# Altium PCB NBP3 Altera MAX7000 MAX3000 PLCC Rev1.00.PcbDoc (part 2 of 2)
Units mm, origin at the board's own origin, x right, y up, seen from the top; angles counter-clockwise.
Board outline 69 x 80.99 mm, 2 copper layers (Top Layer, Bottom Layer); 33 components, 75 nets, 412 pads, 171 vias.
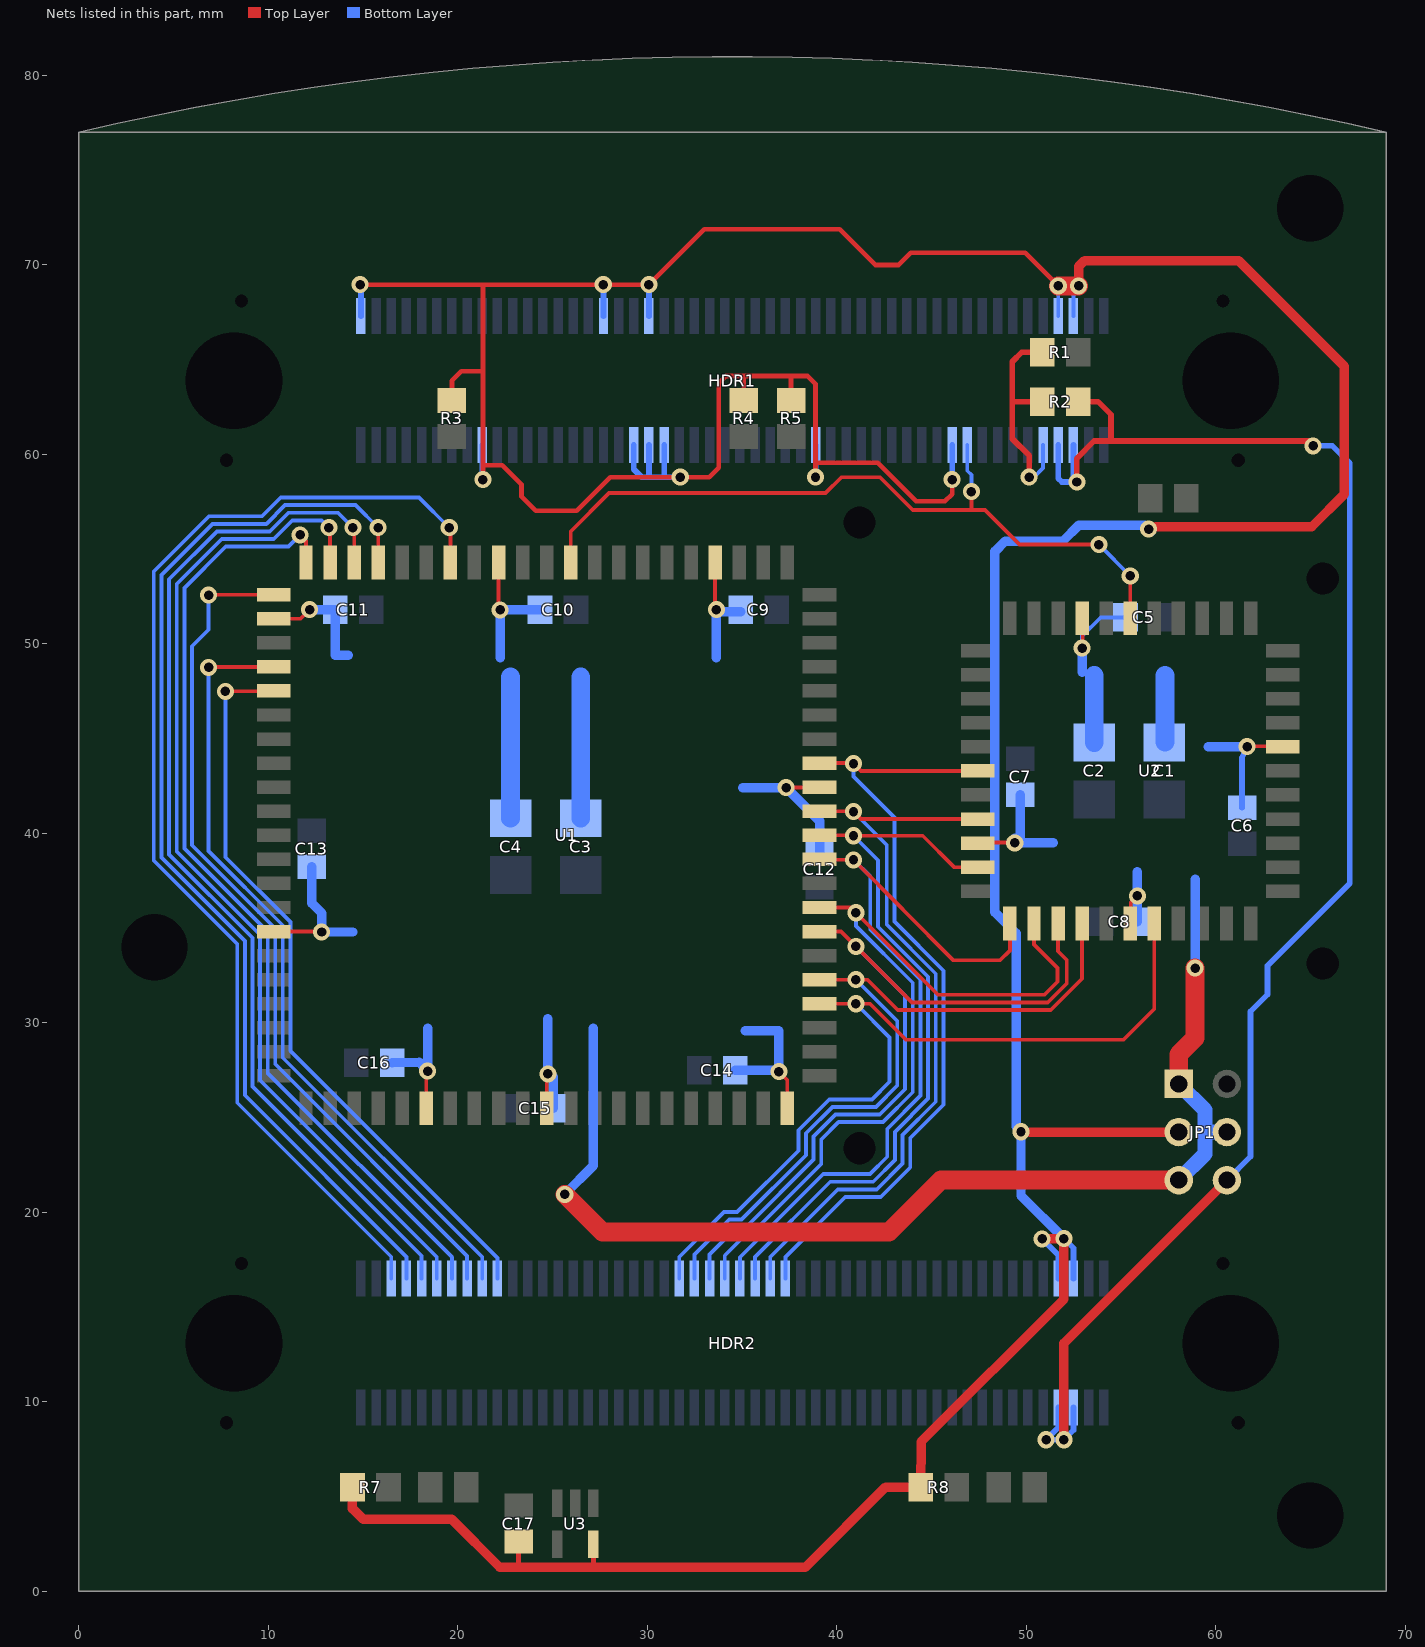
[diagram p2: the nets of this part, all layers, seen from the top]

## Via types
v1: diameter 0.9, hole 0.5, Top Layer to Bottom Layer, 165 vias
v2: diameter 1.27, hole 0.7, Top Layer to Bottom Layer, 6 vias

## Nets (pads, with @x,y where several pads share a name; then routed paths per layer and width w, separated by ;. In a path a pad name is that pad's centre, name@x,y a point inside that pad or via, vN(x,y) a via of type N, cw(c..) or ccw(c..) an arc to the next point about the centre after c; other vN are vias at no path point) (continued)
SW0: HDR2.44 U1.57 U2.24 | length 45.2
  Top Layer w0.2: U1.57@39.1,31.01 41.761,31.01 43.656,29.115 55.15,29.115 56.77,30.735 U2.24@56.77,35.25
  Bottom Layer w0.2: HDR2.44@31.7,16.5 31.7,17.653 34.064,20.017 34.749,20.017 37.986,23.254 37.986,24.338 39.613,25.965 41.865,25.965 42.799,26.899 42.799,29.232 v1(41.021,31.01)
SW1: HDR2.46 U1.58 U2.21 | length 41
  Top Layer w0.2: U1.58@39.1,32.28 41.634,32.28 43.231,30.683 51.308,30.683 52.96,32.335 U2.21@52.96,35.25
  Bottom Layer w0.2: HDR2.46@32.5,16.5 32.5,17.78 34.337,19.617 34.984,19.617 38.386,23.019 38.386,24.172 39.779,25.565 42.075,25.565 43.205,26.695 43.205,30.096 v1(41.021,32.28)
SW2: HDR2.48 U1.60 U2.20 | length 42.9
  Top Layer w0.2: U1.60@39.1,34.82 40.237,34.82 43.974,31.083 51.142,31.083 52.146,32.087 52.146,33.326 51.69,33.782 U2.20@51.69,35.25
  Bottom Layer w0.2: HDR2.48@33.3,16.5 33.3,17.78 34.737,19.217 35.219,19.217 38.786,22.784 38.786,24.007 39.944,25.165 42.278,25.165 43.612,26.499 43.612,31.445 v1(41.021,34.036)
SW3: HDR2.50 U1.61 U2.19 | length 44.5
  Top Layer w0.2: U1.61@39.1,36.09 40.745,36.09 45.352,31.483 50.977,31.483 51.664,32.17 51.664,32.893 50.42,34.137 U2.19@50.42,35.25
  Bottom Layer w0.2: HDR2.50@34.1,16.5 34.1,17.717 35.2,18.817 35.454,18.817 39.192,22.555 39.192,23.847 40.11,24.765 42.443,24.765 44.018,26.34 44.018,32.119 41.021,35.117 v1(41.021,35.814)
SW4: HDR2.52 U1.63 U2.18 | length 42.9
  Top Layer w0.2: U1.63@39.1,38.63 v1(40.894,38.608) 46.139,33.312 48.641,33.312 49.15,33.821 U2.18@49.15,35.25
  Bottom Layer w0.2: HDR2.52@34.9,16.5 34.9,17.628 39.294,22.022 41.758,22.022 42.672,22.936 42.672,24.409 44.425,26.162 44.425,32.279 41.783,34.92 41.783,37.719 v1(40.894,38.608)
SW5: HDR2.54 U1.64 U2.16 | length 39.2
  Top Layer w0.2: U1.64@39.1,39.9 40.872,39.9 v1(40.894,39.878) 44.545,39.878 46.203,38.22 U2.16@47.45,38.22
  Bottom Layer w0.2: HDR2.54@35.7,16.5 35.7,17.653 39.662,21.615 41.935,21.615 43.078,22.758 43.078,24.25 44.831,26.003 44.831,32.438 42.189,35.08 42.189,38.583 v1(40.894,39.878)
SW6: HDR2.56 U1.65 U2.14 | length 39.8
  Top Layer w0.2: U1.65@39.1,41.17 40.872,41.17 41.282,40.76 U2.14@47.45,40.76
  Bottom Layer w0.2: HDR2.56@36.5,16.5 36.5,17.653 40.062,21.215 42.12,21.215 43.485,22.581 43.485,24.091 45.237,25.843 45.237,32.597 42.647,35.188 42.647,39.395 v1(40.894,41.148)
SW7: HDR2.58 U1.67 U2.12 | length 42.2
  Top Layer w0.2: U1.67@39.1,43.71 40.872,43.71 41.282,43.3 U2.12@47.45,43.3
  Bottom Layer w0.2: HDR2.58@37.3,16.5 37.3,17.653 40.462,20.815 42.329,20.815 43.891,22.377 43.891,23.932 45.644,25.684 45.644,32.757 43.053,35.347 43.053,40.841 40.894,43 v1(40.894,43.688)
SWC0: HDR2.18 U1.15 | length 41.7
  Top Layer w0.2: v1(6.858,48.768) 6.88,48.79 U1.15@10.3,48.79
  Bottom Layer w0.2: v1(6.858,48.768) 6.858,39.069 10.775,35.153 10.775,28.163 21.3,17.638 HDR2.18@21.3,16.5
SWC1: HDR2.16 U1.12 | length 45.9
  Top Layer w0.2: v1(6.858,52.578) v1@6.88,52.578 ; v1@6.88,52.6 U1.12@10.3,52.6
  Bottom Layer w0.2: v1(6.858,52.578) 6.858,50.749 5.988,49.879 5.988,39.374 10.375,34.987 10.375,27.827 20.5,17.702 HDR2.16@20.5,16.5
SWC2: HDR2.14 U1.11 | length 51.3
  Top Layer w0.2: v1(11.684,55.753) 12,55.437 U1.11@12,54.3 ; U1.11@12.065,54.102 U1.11@12.065,54.3
  Bottom Layer w0.2: v1(11.684,55.753) 11.068,55.137 7.766,55.137 5.588,52.959 5.588,39.208 9.975,34.821 9.975,27.363 19.7,17.638 HDR2.14@19.7,16.5
SWC3: HDR2.6 U1.5 | length 62.3
  Top Layer w0.2: v1(19.558,56.134) 19.62,56.072 U1.5@19.62,54.3
  Bottom Layer w0.2: HDR2.6@16.5,16.5 16.5,17.663 8.375,25.788 8.375,34.159 3.962,38.571 3.962,53.823 6.877,56.737 9.671,56.737 10.668,57.734 17.958,57.734 v1(19.558,56.134)
SWR0: HDR2.20 U1.16 | length 39.5
  Top Layer w0.2: v1@7.769,47.52 v1(7.747,47.498) U1.16@10.3,47.52
  Bottom Layer w0.2: v1(7.747,47.498) 7.747,38.746 11.175,35.318 11.175,28.525 22.1,17.6 HDR2.20@22.1,16.5
SWR1: HDR2.12 U1.10 | length 53.8
  Top Layer w0.2: v1(13.208,56.134) 13.27,56.072 U1.10@13.27,54.3
  Bottom Layer w0.2: v1(13.208,56.134) 12.827,56.515 11.278,56.515 10.3,55.537 7.556,55.537 5.182,53.162 5.182,39.049 9.575,34.656 9.575,26.978 18.9,17.653 HDR2.12@18.9,16.5
SWR2: HDR2.10 U1.9 | length 55.8
  Top Layer w0.2: U1.9@14.54,54.3 14.54,56.072 v1(14.478,56.134) v1@14.54,56.174
  Bottom Layer w0.2: v1(14.478,56.134) 13.691,56.921 11.074,56.921 10.09,55.937 7.296,55.937 4.775,53.416 4.775,38.89 9.175,34.49 9.175,26.639 18.1,17.714 HDR2.10@18.1,16.5
SWR3: HDR2.8 U1.8 | length 57.8
  Top Layer w0.2: U1.8@15.81,54.3 v1(15.81,56.134)
  Bottom Layer w0.2: v1(15.81,56.134) 14.616,57.328 10.897,57.328 9.906,56.337 7.061,56.337 4.369,53.645 4.369,38.73 8.775,34.324 8.775,26.178 17.3,17.653 HDR2.8@17.3,16.5
TEST: HDR1.81 U1.84 U2.1 | length 40.3
  Top Layer w0.2: U1.84@25.97,54.3 25.97,55.942 27.991,57.963 39.421,57.963 40.259,58.801 42.291,58.801 44.018,57.074 47.828,57.074 49.657,55.245 v1(53.848,55.245) ; 47.117,57.074 v1(47.117,58.039) ; v1(55.499,53.594) v1(55.499,53.594) U2.1@55.5,51.35
  Bottom Layer w0.2: HDR1.81@46.9,60.5 46.9,59.145 47.117,58.928 v1(47.117,58.039) ; v1(53.848,55.245) v1(55.499,53.594)
VCC: C17.1 HDR1.2 HDR1.17 HDR1.34 HDR1.37 HDR1.39 HDR1.40 HDR1.41 HDR1.61 HDR1.79 HDR1.94 HDR1.96 HDR2.94 HDR2.96 JP1.3 R3.1 R4.1 R5.1 R7.1 R8.1 U3.5 | length 264.8
  Top Layer w0.25: v1(14.859,68.961) v1(30.099,68.961) 33.02,71.882 40.157,71.882 42.037,70.002 43.272,70.002 43.919,70.65 49.95,70.65 v1(51.7,68.9) ; R3.1@19.7,62.85 19.7,63.896 20.193,64.389 21.336,64.389 ; v1(21.336,58.674) 21.336,68.961 ; 21.336,59.436 22.352,59.436 23.368,58.42 23.368,57.785 24.13,57.023 26.289,57.023 28.067,58.801 33.274,58.801 33.782,59.309 33.782,63.754 34.163,64.135 38.481,64.135 38.887,63.729 v1(38.887,58.801) ; 23.217,1.27 C17.1@23.217,2.621 ; 27.167,1.27 U3.5@27.167,2.496 ; R4.1@35.1,62.85 35.1,64.135 ; R5.1@37.6,62.85 37.6,64.135 ; 38.887,59.563 42.164,59.563 44.196,57.531 45.72,57.531 46.101,57.912 v1(46.101,58.674)
  Top Layer w0.5: R7.1@14.45,5.5 14.45,4.369 15.009,3.81 19.685,3.81 22.225,1.27 38.354,1.27 42.584,5.5 R8.1@44.45,5.5 44.463,7.892 51.994,15.418 v1(51.994,18.618) ; 50.207,24.24 JP1.3@58.06,24.24 ; v1(50.851,18.6) v1@51.975,18.6 ; v1(52.775,68.9) 52.775,69.92 53.086,70.231 61.214,70.231 66.802,64.643 66.802,57.912 65.075,56.185 56.871,56.185 v1(56.464,56.058)
  Top Layer w1: v1(51.7,68.9) v1(52.775,68.9)
  Bottom Layer w0.2: HDR1.94@51.7,67.3 v1(51.7,68.9) ; HDR1.96@52.5,67.3 52.5,68.625 v1(52.775,68.9)
  Bottom Layer w0.3: HDR1.2@14.9,67.3 v1@14.9,68.92 ; v1@21.3,58.71 HDR1.17@21.3,60.5 ; HDR1.34@27.7,67.3 v1@27.7,68.947 ; HDR1.37@29.3,60.5 29.3,59.219 29.718,58.801 v1(31.75,58.801) ; 30.1,58.801 HDR1.39@30.1,60.5 ; HDR1.40@30.1,67.3 v1(30.099,68.961) ; 30.9,58.801 HDR1.41@30.9,60.5 ; v1@38.9,58.814 HDR1.61@38.9,60.5 ; v1(46.101,58.674) HDR1.79@46.1,60.5 ; v1(50.851,18.6) 51.7,17.751 HDR2.94@51.7,16.5 ; v1(51.994,18.618) 52.5,18.112 HDR2.96@52.5,16.5
  Bottom Layer w0.5: v1(51.994,18.618) 49.733,20.879 v1(49.733,24.257) 49.479,24.511 49.479,34.722 48.359,35.842 48.359,54.887 48.891,55.419 51.939,55.419 52.79,56.27 56.252,56.27 v1@56.591,55.931
  other v1: 27.686,68.961
VCC_FPGA: C1.1 C2.1 C3.1 C4.1 C5.1 C6.1 C7.1 C8.1 C9.2 C10.2 C11.2 C12.1 C13.2 C14.1 C15.1 C16.1 JP1.1 JP1.4 JP1.5 U1.3 U1.13 U1.26 U1.38 U1.43 U1.53 U1.66 U1.78 U2.3 U2.15 U2.23 U2.35 | length 166.8
  Top Layer w0.2: U1.26@10.3,34.82 v1@12.805,34.82 ; U1.13@10.3,51.33 11.706,51.33 v1(12.192,51.816) ; U1.38@18.35,25.5 18.35,27.113 v1(18.415,27.457) ; U1.3@22.16,54.3 22.16,51.881 v1(22.241,51.8) ; 24.7,26.732 U1.43@24.7,25.5 24.7,27.24 v1(24.765,27.305) ; U1.78@33.59,54.3 33.59,51.881 v1(33.655,51.816) ; v1(36.957,27.432) 37.4,26.989 U1.53@37.4,25.5 ; v1(37.338,42.418) 39.078,42.418 U1.66@39.1,42.44 ; U2.15@47.478,39.524 v1@49.122,39.524 ; v1@52.988,49.813 U2.3@52.988,51.384 ; U2.23@55.528,35.284 55.528,36.351 v1(55.88,36.703) ; v1(61.671,44.577) 62.003,44.604 U2.35@63.578,44.604
  Top Layer w1: v1(25.654,20.955) 27.635,18.974 42.774,18.974 45.5,21.7 JP1.5@58.06,21.7 ; JP1.1@58.06,26.78 58.06,28.342 58.928,29.21 v1(58.928,32.893)
  Bottom Layer w0.2: v1(52.959,49.784) 52.959,50.419 53.94,51.4 C5.1@55.25,51.4
  Bottom Layer w0.3: C6.1@61.4,41.35 61.4,44.001 v1(61.671,44.577)
  Bottom Layer w0.5: v1@12.208,51.8 C11.2@13.55,51.8 13.55,49.403 14.224,49.403 ; C13.2@12.3,38.25 12.3,36.322 12.827,35.795 v1(12.827,34.798) 14.478,34.798 ; C16.1@16.55,27.9 17.983,27.915 v1@18.372,27.5 ; v1(18.415,27.457) 18.415,29.718 ; 22.241,49.276 v1(22.241,51.8) C10.2@24.35,51.8 ; v1(24.765,27.305) 24.765,30.226 ; C15.1@25.05,25.5 v1@25.05,27.15 ; v1(25.654,20.955) 27.153,22.454 27.153,29.718 ; 33.655,49.276 v1(33.655,51.816) 33.771,51.7 C9.2@34.95,51.7 ; C14.1@34.65,27.5 36.889,27.5 v1(36.957,27.432) 36.957,29.591 35.179,29.591 ; 35.052,42.418 v1(37.338,42.418) 39.1,40.656 C12.1@39.1,39.05 ; v1@49.4,39.748 v1(49.403,39.497) ; C7.1@49.7,42.05 49.7,39.794 v1(49.403,39.497) ; 51.435,39.497 v1(49.403,39.497) ; 52.959,48.514 v1(52.959,49.784) ; C8.1@55.878,35.334 v1@55.878,36.701 ; v1(55.88,36.703) 55.88,37.973 ; v1(58.928,32.893) 58.928,37.592 ; 59.614,44.577 v1(61.671,44.577)
  Bottom Layer w0.8: JP1.5@58.06,21.7 59.436,23.076 59.436,25.404 JP1.1@58.06,26.78 ; 59.453,24.24 JP1.4@60.6,24.24
  Bottom Layer w1: C4.1@22.8,40.8 22.8,48.26 ; C3.1@26.5,40.8 26.5,48.26 ; C2.1@53.6,44.8 53.6,48.325 ; C1.1@57.328,44.834 57.328,48.336
VCCINT: HDR1.93 HDR1.95 HDR2.93 HDR2.95 JP1.6 R2.1 | length 90.3
  Top Layer w0.3: v1(52.68,58.547) 52.68,59.792 53.594,60.706 64.897,60.706 v1(65.151,60.452) ; R2.1@52.75,62.787 53.799,62.787 54.483,62.103 54.483,60.706
  Top Layer w0.5: v1(51.994,8.001) 51.994,13.094 JP1.6@60.6,21.7
  Bottom Layer w0.3: HDR1.93@51.7,60.5 51.7,58.739 51.892,58.547 v1(52.68,58.547) 52.5,58.727 HDR1.95@52.5,60.5 ; HDR2.95@52.5,9.7 52.5,8.507 v1(51.994,8.001) ; JP1.6@60.6,21.7 61.849,22.949 61.849,30.607 62.738,31.496 62.738,33.02 67.081,37.363 67.081,59.538 66.167,60.452 v1(65.151,60.452) ; v1(51.054,8.001) 51.7,8.647 ; v1(51.054,8.001) v1(51.994,8.001) ; v1(51.054,8.001) 51.7,8.647 ; v1(51.054,8.001) v1(51.994,8.001) ; 51.7,8.647 HDR2.93@51.7,9.7 51.7,8.647
VREF: HDR1.91 R1.1 R2.2 | length 12
  Top Layer w0.3: 49.276,62.787 R2.2@50.85,62.787 ; v1(50.165,58.801) 50.165,59.944 49.276,60.833 49.276,64.897 49.779,65.4 R1.1@50.85,65.4
  Bottom Layer w0.2: v1(50.165,58.801) 50.419,58.801 50.9,59.282 HDR1.91@50.9,60.5
pads on no net: HDR1.3 HDR1.4 HDR1.5 HDR1.6 HDR1.8 HDR1.9 HDR1.10 HDR1.11 HDR1.12 HDR1.13 HDR1.14 HDR1.16 HDR1.18 HDR1.20 HDR1.22 HDR1.24 HDR1.26 HDR1.28 HDR1.30 HDR1.32 HDR1.43 HDR1.44 HDR1.45 HDR1.46 HDR1.47 HDR1.48 HDR1.49 HDR1.50 HDR1.51 HDR1.52 HDR1.53 HDR1.55 HDR1.56 HDR1.57 HDR1.58 HDR1.60 HDR1.62 HDR1.64 HDR1.66 HDR1.68 HDR1.76 HDR1.80 HDR1.82 HDR1.83 HDR1.84 HDR1.85 HDR1.86 HDR1.87 HDR1.88 HDR1.89 HDR1.90 HDR1.92 HDR1.MH1 HDR1.MH2 HDR1.MH3 HDR1.MH4 HDR1.MH5 HDR1.MH6 HDR2.3 HDR2.5 HDR2.43 HDR2.45 HDR2.47 HDR2.49 HDR2.51 HDR2.53 HDR2.55 HDR2.57 HDR2.59 HDR2.61 HDR2.63 HDR2.65 HDR2.67 HDR2.69 HDR2.71 HDR2.73 HDR2.75 HDR2.76 HDR2.77 HDR2.78 HDR2.79 HDR2.80 HDR2.81 HDR2.82 HDR2.83 HDR2.84 HDR2.85 HDR2.86 HDR2.87 HDR2.88 HDR2.89 HDR2.90 HDR2.91 HDR2.92 HDR2.MH1 HDR2.MH2 HDR2.MH3 HDR2.MH4 HDR2.MH5 HDR2.MH6 U1.6 U1.39 U1.46 U1.79 U1.M1 U1.M2 U2.M1 U2.M2 U3.1

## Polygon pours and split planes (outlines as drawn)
GND on Top Layer "Top Layer-GND" (solid, remove dead copper, pour order 1000): 0.127,80.518 68.834,80.645 68.834,0.127 0.127,0.127
GND on Bottom Layer "Bottom Layer-GND" (solid, remove dead copper, pour order 1001): 0.127,80.518 68.834,80.645 68.834,0.127 0.127,0.127

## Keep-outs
Keep-Out Layer:
  the board outline again, w0.8

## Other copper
Bottom Layer:
  rectangle net VCC_FPGA: 33.655,29.21 35.56,48.133
  rectangle net VCC_FPGA: 13.97,29.21 15.875,48.133
  rectangle net VCC_FPGA: 13.97,47.752 35.56,49.657
  rectangle net VCC_FPGA: 15.494,29.21 34.036,31.115
  region net VCC_FPGA: 51.816,48.133 50.673,48.133 50.673,38.608 51.816,38.608
  rectangle net VCC_FPGA: 59.182,38.608 60.325,48.133
  rectangle net VCC_FPGA: 50.673,37.465 60.325,38.735
  rectangle net VCC_FPGA: 50.673,47.752 60.325,49.022

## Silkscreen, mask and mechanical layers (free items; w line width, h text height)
Top Overlay:
  circle w0.127: c4,34 r2.5
  circle w0.127: c65,4 r2.5
  circle w0.127: c65,73 r2.5
  lines w0.127: 0,1.5 1.5,1.5 1.5,0 ; 0,22.3 1.5,22.3 1.5,23.4 0,23.4 ; 0.001,53.6 1.501,53.6 1.501,54.7 0.001,54.7 ; 0,75.5 1.5,75.5 1.5,77.3 ; 15.7,79.8 15.7,78.1 17,78.1 17,79.9 ; 49.7,80.2 49.7,78.7 51,78.7 51,80.1 ; 67.5,0 67.5,1.5 69,1.5 ; 67.5,77.3 67.5,75.5 69,75.5 ; 68.999,22.3 67.5,22.3 67.5,23.4 69,23.4 ; 69,53.6 67.501,53.6 67.501,54.7 69.001,54.7
  lines w0.2: 43.963,21.7 54.885,21.7 56.155,22.97 56.409,22.97 ; 43.963,26.78 54.885,26.78 56.155,25.51 56.409,25.51 ; 56.409,20.43 56.155,20.43 54.885,19.16 43.963,19.16 43.963,29.32 54.885,29.32 56.155,28.05 56.409,28.05 ; 62.251,20.43 66.188,20.43 66.188,28.05 62.251,28.05 ; 62.251,22.97 66.188,22.97 ; 62.251,25.51 66.188,25.51
  text "MAX7000S" at 44.852,27.415 h1.2
  text "5V" at 63.14,26.145 h1.2
  text "MAX3000A" at 44.852,24.875 h1.2
  text "3V3" at 62.632,23.605 h1.2
  text "MAX7000AE" at 44.852,22.335 h1.2
  text "2V5" at 62.632,21.065 h1.2
  text "MAX7000B" at 44.852,19.795 h1.2
Bottom Overlay:
  drawing of 853 lines, arcs and shapes, not listed
  text "REV 1.00" at 47.6,76.5 h1.3
  text "NBP3" at 54.5,76.5 h1.3
  text "1" at 13.97,58.42 h1
  text "1" at 14.224,7.62 h1
PCB Boundary:
  the board outline again, w0.25
  text "PCB boundary coincides with centre-line of tracks and arc" at 0,-12 h0.75
Gerber ID:
  text ".Layer_Name" at 0,-6 h0.75
Printout ID:
  text ".Printout_Name" at 0,-10 h0.75
Design Information:
  drawing of 713 lines, arcs and shapes, not listed
  text "BOCD_1_00_Daughter_NBP3" at 317.627,202.041 h1.27
  text "DESIGN INFORMATION" at 261.62,201.914 h1.52
  text "BOARD NAME:" at 299.212,201.914 h1.52
  text "BOARD TECHNOLOGY" at 261.62,199.374 h1.52
  text "BOARD SIZE (REFER ALSO PROFILING INFORMATION)" at 309.88,199.374 h1.27
  text "69.00mm" at 312.6,197.1 h1.52
  text "19.685" at 277.419,197.012 h1.52
  text "81.00mm" at 335.6,197 h1.52
  text "7.874" at 291.389,196.885 h1.52
  text "7.874" at 264.446,196.834 h1.52
  text "X" at 328.549,196.326 h1.78
  text "(MIN. TRACK/   PADS  /   CLEARANCE     IN 0.001'')" at 260.096,194.294 h1.27
  text "MINIMUM ANNULAR RING 0.05MM (0.002'') EXTERNAL PER IPC-2221 CLASS 3 LEVEL C AND IS THE" at 261.62,191.754 h1.27
  text "MANUFACTURING REGISTRATION ALLOWANCE" at 261.62,189.468 h1.27
  text "LAND SIZE CALCULATION MINIMUM - NOMINAL HOLE SIZE + 0.508MM (0.020'')" at 261.62,186.674 h1.27
  text "AS INSTRUCTED" at 347.65,182.28 h1.52
  text "X" at 299.263,182.153 h1.52
  text "CIRCUIT TYPE:" at 261.62,182.102 h1.52
  text "SS" at 284.48,182.102 h1.27
  text "DS" at 302.26,182.102 h1.27
  text "X" at 316.865,182.102 h1.52
  text "PTH" at 320.04,182.102 h1.27
  text "ML" at 330.962,182.102 h1.27
  text "No. OFF" at 337.82,182.102 h1.27
  text "FINGER CONNECTOR DIM PER:" at 261.62,179.054 h1.52
  text "AS SHOWN" at 337.82,179.054 h1.27
  text "No. OFF TOTAL" at 278.384,176.26 h1.52
  text "ONE SIDE" at 320.04,176.26 h1.27
  text "BOTH SIDES" at 337.82,176.006 h1.27
  text "VIAS:" at 261.62,173.339 h1.52
  text "NONE" at 273.05,173.339 h1.14
  text "X" at 281.432,173.339 h1.52
  text "FEED THRU'" at 284.48,173.339 h1.14
  text "X" at 299.212,173.339 h1.52
  text "TENTED" at 302.26,173.339 h1.14
  text "UNIQUE DRILL" at 284.48,170.291 h1.14
  text "2 SIZE" at 302.26,170.291 h1.14
  text "BLIND LAYER SEQUENCE" at 320.04,170.291 h1.14
  text "Layer Stack Manager (Protel)" at 297.053,168.005 h1.27
  text "X" at 334.772,168.005 h1.52
  text "AS SHOWN" at 337.82,168.005 h1.27
  text "LAYER CONSTRUCTION PER:" at 261.62,167.878 h1.52
  text "Protel" at 342.646,165.338 h1.27
  text "(PFW)" at 352.933,165.211 h1.27
  text "ARTWORK:" at 261.62,165.084 h1.52
  text "MANUAL" at 284.48,165.084 h1.27
  text "DIGITISED" at 302.26,165.084 h1.27
  text "X" at 316.992,165.084 h1.52
  text "CAD" at 320.04,165.084 h1.27
  text "TYPE" at 330.962,165.084 h1.27
  text "ARTWORK/PATTERN MASTER LIST" at 261.62,160.385 h1.52
  text "DESCRIPTION" at 262.89,157.972 h1.27
  text "DRAWING No./CAD FILE REF." at 281.559,157.972 h1.27
  text "LAYER NAME" at 322.834,157.972 h1.27
  text "GERBER FILE REF" at 343.586,157.896 h1.27
  text "PCB FILE" at 261.366,155.432 h1.27
  text "BOCD_1_00_Daughter_NBP3" at 281.237,155.356 h1.27
  text "PcbDoc" at 312.979,155.356 h1.02
  text "Top Paste Mask" at 321.158,152.892 h1.02
  text "GTP" at 363.779,152.816 h1.27
  text "GERBER FILE" at 261.366,152.765 h1.27
  text "GTO" at 363.728,150.327 h1.27
  text "Top Overlay" at 321.158,150.301 h1.02
  text "GERBER FILE" at 261.366,150.225 h1.27
  text "Top Solder Mask" at 321.158,147.863 h1.02
  text "GTS" at 363.779,147.736 h1.27
  text "GERBER FILE" at 261.366,147.685 h1.27
  text "TOP LAYER" at 321.158,145.272 h1.02
  text "GTL" at 363.779,145.196 h1.27
  text "GERBER FILE" at 261.366,145.145 h1.27
  text "BOTTOMLAYER" at 321.158,142.732 h1.02
  text "GBL" at 363.779,142.656 h1.27
  text "GERBER FILE" at 261.366,142.605 h1.27
  text "Bottom Solder Mask" at 321.158,140.243 h1.02
  text "GBS" at 363.779,140.116 h1.27
  text "GERBER FILE" at 261.366,140.065 h1.27
  text "Bottom Overlay" at 321.158,137.652 h1.02
  text "GBO" at 363.779,137.576 h1.27
  text "GERBER FILE" at 261.366,137.525 h1.27
  text "Bottom Paste Mask" at 321.158,135.163 h1.02
  text "GBP" at 363.779,135.036 h1.27
  text "GERBER FILE" at 261.366,134.985 h1.27
  text "PCB Boundary" at 321.158,132.572 h1.02
  text "GM1" at 363.779,132.496 h1.27
  text "GERBER FILE" at 261.366,132.445 h1.27
  text "APERTURE LIST" at 261.366,130.032 h1.27
  text "APR" at 313.979,129.956 h1.27
  text "DRILL REPORT" at 261.366,127.492 h1.27
  text "DRR" at 313.979,127.416 h1.27
  text "EXCELLON DRILL" at 261.366,124.952 h1.27
  text "TXT" at 313.979,124.876 h1.27
  text "MATERIAL:" at 261.62,99.298 h1.52
  text "GLASS FIBRE EPOXY RESIN NEMA GRADE FR4 (MIL-S-13949H)" at 287.274,99.044 h1.27
  text "X" at 284.607,98.917 h1.52
  text "THICKNESS:" at 269.494,96.123 h1.27
  text "0.8mm" at 287.274,96.123 h1.27
  text "1.2mm" at 304.927,96.123 h1.27
  text "1.6mm" at 322.58,96.123 h1.27
  text "2.4mm" at 340.36,96.123 h1.27
  text "3.2mm" at 358.14,96.123 h1.27
  text "X" at 320.167,95.996 h1.52
  text "TOLERANCE:" at 269.367,93.075 h1.27
  text "IN A/W IPC-D-300G CLASS" at 287.02,93.075 h1.27
  text "3 LEVEL B" at 321.945,93.075 h1.27
  text "OTHER +/-" at 340.36,93.075 h1.27
  text "X" at 284.607,92.948 h1.52
  text "BOW & TWIST:" at 266.954,90.027 h1.27
  text "IN A/W IPC-D-300G CLASS" at 287.02,90.027 h1.27
  text "3 LEVEL B" at 321.945,90.027 h1.27
  text "AS SHOWN" at 340.487,89.9 h1.27
  text "X" at 284.607,89.773 h1.52
  text "COPPER THICKNESS (FINISHED)" at 269.367,86.725 h1.27
  text "OUTER:" at 274.193,84.439 h1.27
  text "18um" at 287.274,84.439 h1.27
  text "35um" at 314.325,84.439 h1.27
  text "70um" at 340.614,84.439 h1.27
  text "X" at 311.582,84.236 h1.52
  text "INNER SIGNAL:" at 265.811,81.391 h1.27
  text "18um" at 287.274,81.391 h1.27
  text "35um" at 314.325,81.391 h1.27
  text "70um" at 340.614,81.391 h1.27
  text "INNER PWR:" at 269.494,78.343 h1.27
  text "18um" at 287.274,78.343 h1.27
  text "35um" at 314.325,78.343 h1.27
  text "70um" at 340.614,78.343 h1.27
  text "STRUCTURE:" at 261.62,75.295 h1.52
  text "REFER" at 287.274,75.295 h1.27
  text "AS PER DRAWING No." at 287.147,72.12 h1.27
  text "AS SHOWN" at 340.487,72.12 h1.27
  text "X" at 337.947,71.993 h1.52
  text "DRILLING:" at 261.62,69.326 h1.52
  text "VIEWED FROM:" at 266.573,67.04 h1.27
  text "COMPONENT SIDE" at 287.274,67.04 h1.14
  text "SOLDER SIDE" at 314.071,67.04 h1.14
  text "X" at 284.607,66.786 h1.52
  text "REFERENCE:" at 268.859,63.992 h1.27
  text "AS SHOWN" at 287.147,63.865 h1.14
  text "PATTERN MASTER LIST" at 314.198,63.865 h1.14
  text "X" at 337.947,63.865 h1.52
  text "NC_DRILL FILES" at 340.487,63.865 h1.14
  text "X" at 284.607,63.738 h1.52
  text "PTH MINIMUM COPPER THICKNESS:" at 274.701,60.944 h1.27
  text "20um" at 314.325,60.944 h1.27
  text "X" at 311.658,60.817 h1.52
  text "OTHER" at 340.487,60.817 h1.27
  text "NPTH:" at 275.209,57.896 h1.27
  text "TENTED" at 287.147,57.769 h1.14
  text "X" at 311.658,57.769 h1.52
  text "PADS REMOVED" at 314.198,57.769 h1.14
  text "REMOVE PADS" at 340.487,57.769 h1.14
  text "X" at 284.607,57.642 h1.52
  text "2nd DRILL" at 287.147,54.721 h1.14
  text "BOTH" at 314.198,54.721 h1.14
  text "AS SHOWN" at 326.517,54.721 h1.14
  text "NONE" at 340.487,54.721 h1.14
  text "BOARD FINISH:" at 261.62,51.8 h1.52
  text "X" at 284.607,51.673 h1.52
  text "ETCHING" at 287.147,51.673 h1.14
  text "REFER PATTERN MASTER LIST" at 314.198,51.673 h1.14
  text "LEGEND / SCREEN PRINT:" at 281.94,48.752 h1.27
  text "NONE" at 314.198,48.625 h1.14
  text "COMPONENT" at 326.517,48.625 h1.14
  text "SOLDER" at 340.487,48.625 h1.14
  text "X" at 323.977,48.498 h1.52
  text "X" at 337.947,48.498 h1.52
  text "COLOUR:" at 272.161,45.704 h1.27
  text "WHITE" at 287.147,45.577 h1.14
  text "YELLOW" at 314.198,45.577 h1.14
  text "OTHER" at 340.487,45.577 h1.14
  text "X" at 284.607,45.45 h1.52
  text "X" at 284.607,42.529 h1.52
  text "LIQUID PHOTOIMAGEABLE" at 287.147,42.529 h1.14
  text "SCREEN PRINT" at 326.517,42.529 h1.14
  text "MATTE" at 287.147,39.481 h1.14
  text "GLOSS" at 299.847,39.481 h1.14
  text "GREEN" at 314.198,39.481 h1.14
  text "BLUE" at 326.517,39.481 h1.14
  text "G/Y" at 340.487,39.481 h1.14
  text "OTHER" at 351.917,39.481 h1.14
  text "X" at 297.18,39.354 h1.52
  text "SOLDER MASK COLOUR:" at 261.62,36.56 h1.14
  text "BLACK" at 287.147,36.433 h1.14
  text "GREEN" at 299.847,36.433 h1.14
  text "YELLOW" at 314.198,36.433 h1.14
  text "BLUE" at 326.517,36.433 h1.14
  text "OTHER" at 340.487,36.433 h1.14
  text "X" at 284.48,36.306 h1.52
  text "TRACK FINISH:" at 261.62,33.512 h1.52
  text "X" at 284.607,33.385 h1.52
  text "SELECTIVE SOLDER (HASL)" at 287.147,33.385 h1.14
  text "REFLOW SOLDER" at 326.517,33.385 h1.14
  text "SELECTIVE GOLD" at 287.147,30.337 h1.14
  text "um  (AREA" at 314.198,30.337 h1.14
  text "sq. mm)" at 342.011,30.337 h1.14
  text "REFER PATTERN MASTER LIST" at 287.147,27.289 h1.14
  text "OTHER" at 326.517,27.289 h1.14
  text "EDGE BOARD" at 261.62,24.368 h1.52
  text "1.3um HARD GOLD OVER 5um     NICKEL / TIN-NICKEL" at 287.147,24.241 h1.14
  text "CONTACTS:" at 261.62,22.209 h1.52
  text "HARD FINISH GOLDE PLATE" at 287.147,21.193 h1.14
  text "OTHER" at 326.517,21.193 h1.14
  text "AS SHOWN" at 287.147,18.145 h1.14
  text "REFER" at 326.517,18.145 h1.14
  text "PROFILING:" at 261.62,15.097 h1.52
  text "AS DIMENSIONED, MEASURED AND CUT FROM SPECIFIED DATUM." at 287.147,15.097 h1.14
  text "X" at 284.607,14.97 h1.52
  text "REFER PCB BLANK DWG No." at 287.274,12.176 h1.27
  text "USE PROFILE / ROUTE TAPE SUPPLIED (REFER PATTERN MASTER LIST)" at 287.274,9.128 h1.27
  text "SQUARE CUT" at 287.274,6.08 h1.27
  text "N.C. ROUTE" at 305.054,6.08 h1.27
  text "V. SCORE" at 322.834,6.08 h1.27
  text "BLANK" at 340.614,6.08 h1.27
  text "ACCEPTABILITY:" at 261.62,3.413 h1.52
  text "MATERIALS AND WORKMANSHIP FOR ALL PRINTED WIRING BOARDS TO MEET" at 283.845,3.286 h1.27
  text "OR EXCEED THE REQUIREMENTS OF:" at 283.845,0.492 h1.27
  text "IPC-6011/12 AND IPC-A-600E" at 287.401,-2.175 h1.27
  text "1" at 322.961,-2.175 h1.27
  text "2" at 331.851,-2.175 h1.27
  text "X" at 329.184,-2.302 h1.52
  text "X" at 284.734,-2.429 h1.52
  text "3" at 340.741,-4.334 h1.27
  text "UL CERTIFICATION" at 287.401,-5.223 h1.27
  text "AUSTEL" at 322.961,-5.223 h1.27
  text "X" at 284.734,-5.35 h1.52
  text "ML-P-55110F GRP" at 286.893,-8.271 h1.02
  text "A" at 305.181,-8.271 h1.27
  text "B" at 314.071,-8.271 h1.27
  text "AS2546" at 322.961,-8.271 h1.27
  text "OTHER" at 340.741,-8.271 h1.27
  text "ADDITIONAL" at 261.62,-11.192 h1.52
  text "NONE" at 287.401,-11.446 h1.27
  text "SAMPLE PLAN" at 305.181,-11.446 h1.27
  text "MIL-P-55110E SERIAL Nos. PER ORDER" at 322.961,-11.446 h1.27
  text "REQUIREMENTS:" at 261.62,-13.605 h1.52
  text "NONE" at 287.401,-14.494 h1.27
  text "ML-P-55110F GRP" at 304.673,-14.494 h1.02
  text "A" at 322.961,-14.494 h1.27
  text "B" at 331.851,-14.494 h1.27
  text "IPC CLASS:" at 337.82,-14.494 h1.27
  text "1" at 353.314,-14.494 h1.27
  text "2" at 359.664,-14.494 h1.27
  text "3" at 366.014,-14.494 h1.27
  text "QUALITY RELEASE REPORT" at 305.181,-17.542 h1.27
  text "OTHER" at 345.694,-17.542 h1.27
  text "PER ORDER" at 354.203,-17.669 h1.27
  text "X" at 343.027,-17.796 h1.52
  text "NONE" at 305.181,-20.59 h1.27
  text "REQUIRED" at 322.961,-20.59 h1.27
  text "PER ORDER" at 345.821,-20.59 h1.27
  text "ELECTRICAL TEST:" at 261.62,-20.717 h1.52
  text "X" at 320.294,-20.717 h1.52
  text "NONE" at 305.181,-23.638 h1.27
  text "1 SIDE" at 322.834,-23.638 h1.14
  text "2 SIDES" at 334.01,-23.638 h1.14
  text "MIN. PITCH" at 345.694,-23.638 h1.27
  text "0.80mm" at 359.283,-23.638 h1.27
  text "SURFACE MOUNT:" at 261.62,-23.765 h1.52
  text "X" at 331.775,-23.841 h1.52
  text "NONE" at 305.181,-26.686 h1.27
  text "FOIL" at 322.961,-26.686 h1.27
  text "LEGEND" at 334.391,-26.686 h1.27
  text "REFER" at 345.694,-26.686 h1.27
  text "MANUFACTURER'S ID/LOGO:" at 261.62,-26.813 h1.52
  text "ISO9001/AS3901" at 308.991,-29.734 h1.27
  text "NONE" at 345.694,-29.734 h1.27
  text "MANUFACTURER'S ACCREDITATION:" at 261.62,-29.861 h1.52
  text "X" at 306.324,-29.861 h1.52
  text "PER ORDER" at 305.181,-32.782 h1.27
  text "REFER" at 322.961,-32.782 h1.27
  text "PACKAGING AND HANDLING:" at 261.62,-32.909 h1.52
  text "X" at 302.514,-33.036 h1.52
Sheet:
  drawing of 1882 lines, arcs and shapes, not listed
  text "1" at 3.717,207.391 h1.78
  text "2" at 52.756,207.391 h1.78
  text "3" at 102.015,207.391 h1.78
  text "4" at 151.308,207.391 h1.78
  text "5" at 200.584,207.391 h1.78
  text "6" at 249.606,207.391 h1.78
  text "7" at 299.136,207.391 h1.78
  text "8" at 348.158,207.391 h1.78
  text "A" at -18.415,173.406 h1.78
  text "A" at 370.205,173.406 h1.78
  text "B" at -18.415,102.794 h1.78
  text "B" at 370.205,102.794 h1.78
  text "C" at -18.415,32.182 h1.78
  text "C" at 370.205,32.182 h1.78
  text "D" at -18.415,-37.922 h1.78
  text "D" at 370.205,-37.922 h1.78
  text "ENGINEER:" at 255.27,-38.1 h1.14
  text "TITLE:" at 293.37,-38.1 h1.14
  text "PCB DESIGNER:" at 255.27,-45.593 h1.14
  text "DATE:" at 255.27,-53.34 h1.14
  text "PART NO.:" at 293.37,-53.34 h1.14
  text "REV:" at 346.71,-53.34 h1.14
  text "Altium Limited" at 222.25,-55.88 h1.78
  text ".PRINT_DATE" at 256.54,-56.388 h1.78
  text "12a Rodborough Rd" at 222.25,-58.42 h1.78
  text "Frenchs Forest" at 222.25,-60.96 h1.78
  text "FILE NAME:" at 255.27,-60.96 h1.14
  text "DWG NO:" at 293.37,-60.96 h1.14
  text "SCALE:" at 346.71,-60.96 h1.14
  text "NSW 2086" at 222.25,-63.5 h1.78
  text ".PCB_FILE_NAME_NO_PATH" at 256.54,-64.008 h1.78
  text "1" at 3.717,-69.469 h1.78
  text "2" at 52.756,-69.469 h1.78
  text "3" at 102.015,-69.469 h1.78
  text "4" at 151.308,-69.469 h1.78
  text "5" at 200.584,-69.469 h1.78
  text "6" at 249.606,-69.469 h1.78
  text "7" at 299.136,-69.469 h1.78
  text "8" at 348.158,-69.469 h1.78
Drill Drawing:
  text ".Legend" at 0,-8 h0.75

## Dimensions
34.5,-69.801 to 34.5,84 on Dimensions
0,0 to 0.001,77 on Dimensions
0,0 to 69,0 on Dimensions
